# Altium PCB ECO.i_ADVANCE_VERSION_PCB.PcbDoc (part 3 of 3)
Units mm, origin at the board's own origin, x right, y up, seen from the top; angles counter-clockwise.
Board outline 291.08 x 101.6 mm, 4 copper layers (Top Layer, Layer 1, Layer 2, Bottom Layer), stack 1.161 mm thick; 272 components, 228 nets, 849 pads, 240 vias.
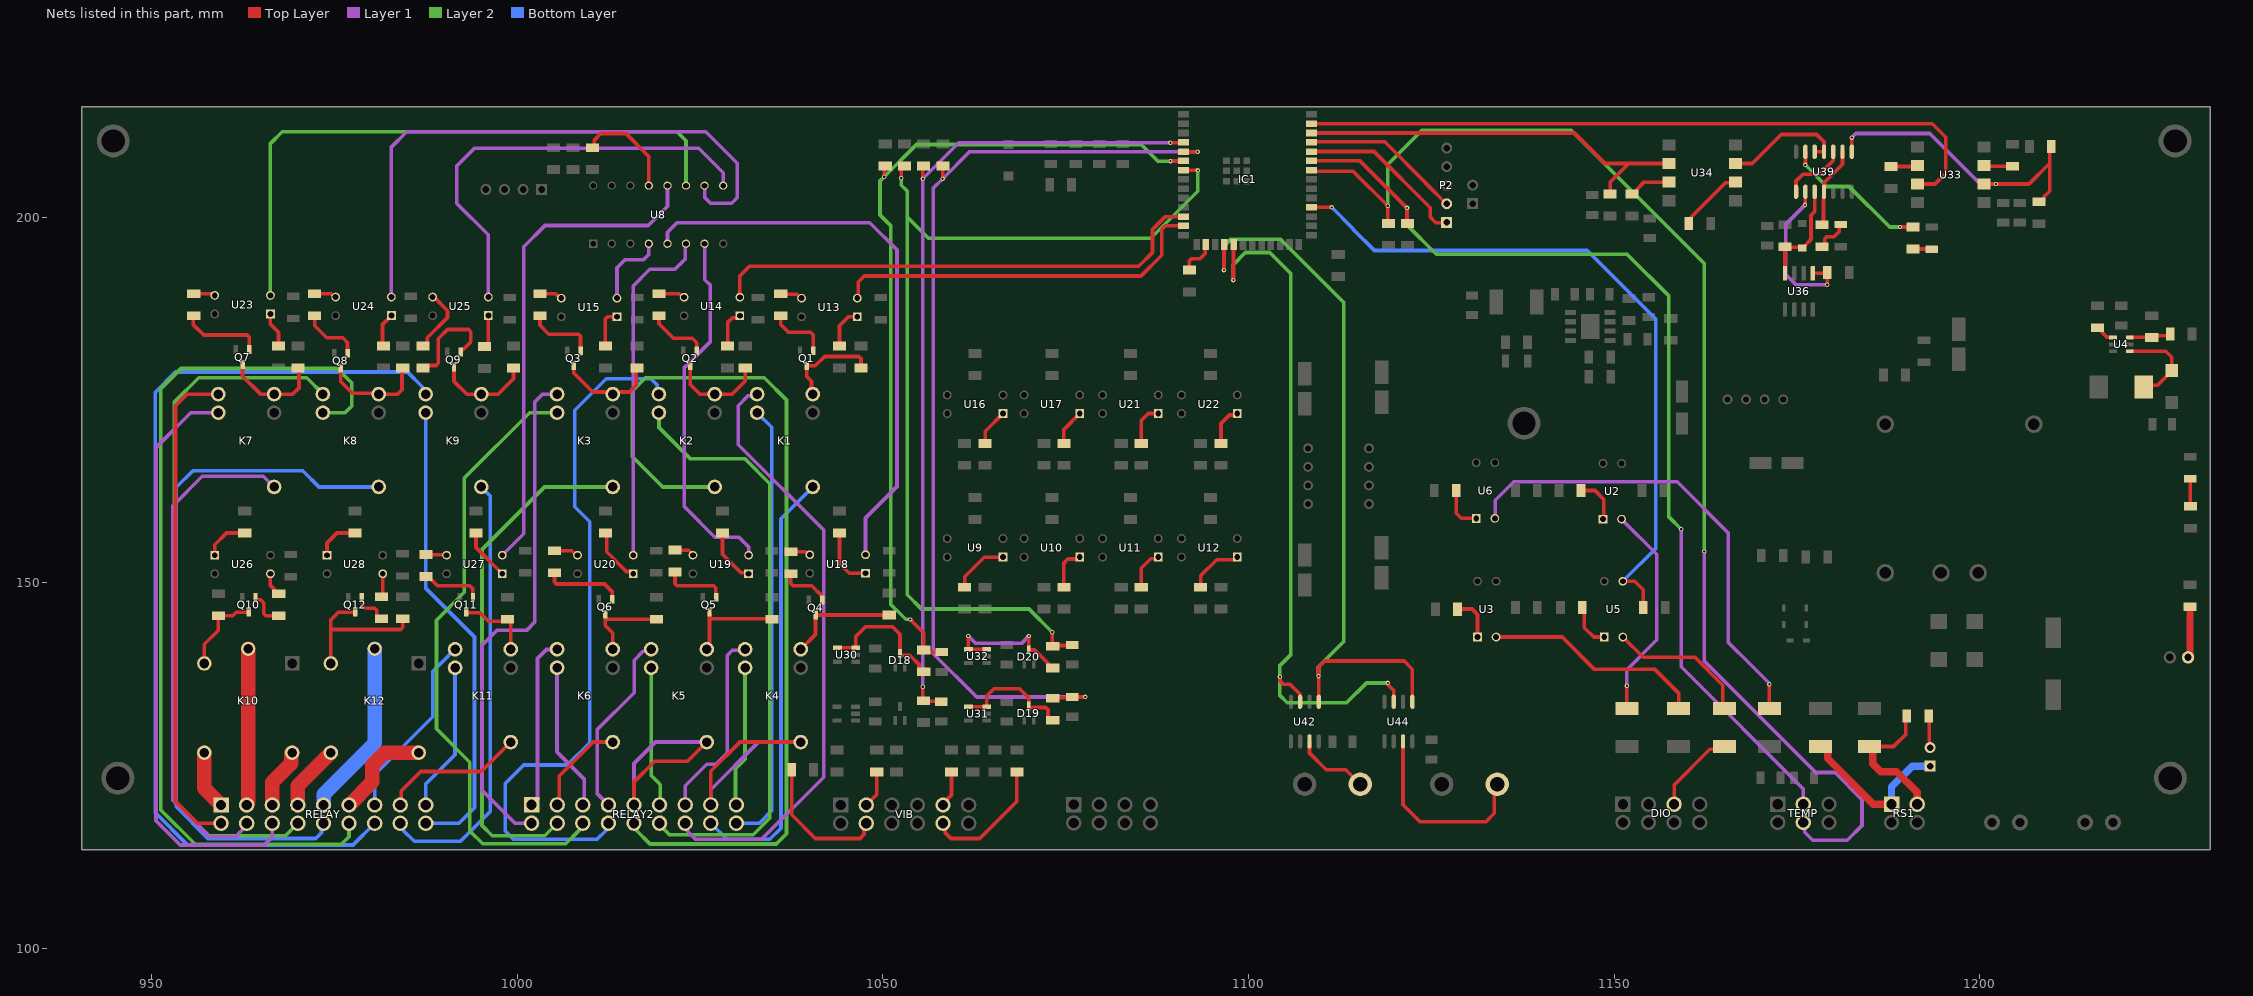
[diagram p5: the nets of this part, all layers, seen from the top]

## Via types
v1: diameter 0.6, hole 0.3, Top Layer to Bottom Layer, 154 vias
v2: diameter 1.27, hole 0.711, Top Layer to Bottom Layer, 80 vias
v3: diameter 2.4, hole 1.6, Top Layer to Bottom Layer, 4 vias
v4: diameter 1.5, hole 1, Top Layer to Bottom Layer, 2 vias

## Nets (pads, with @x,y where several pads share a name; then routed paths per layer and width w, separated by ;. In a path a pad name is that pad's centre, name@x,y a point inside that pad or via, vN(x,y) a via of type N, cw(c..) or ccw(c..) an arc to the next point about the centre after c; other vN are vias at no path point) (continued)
NetD18_3: D18.3 R84.1 U30.3 U30.4 | length 18.5
  Top Layer w0.5: U30.4@1043.774,141.128 U30.3@1046.285,141.128 1046.285,142.68 1047.623,144.018 1051.306,144.018 1052.347,142.977 D18.3@1052.347,140.354 1052.347,140.127 1053.673,140.127 1054.942,138.858 1054.942,138.195 1055.292,137.845 R84.1@1055.592,137.845
NetD19_3: D19.3 R90.1 U31.3 U31.4 | length 16.6
  Top Layer w0.5: U31.4@1061.691,133.081 U31.3@1064.201,133.081 1064.201,134.561 1065.149,135.509 1068.705,135.509 1069.961,134.253 1069.961,132.969 1072.274,132.969 1072.567,132.676 1072.567,131.58 1072.917,131.23 R90.1@1073.217,131.23
NetD20_3: D20.3 R91.1 U32.3 U32.4 | length 19.8
  Top Layer w0.5: v1(1061.673,142.738) 1061.673,140.975 1061.697,140.951 U32.4@1061.691,140.945 U32.3@1064.201,140.945 ; v1(1069.961,142.748) D20.3@1069.961,140.83 1070.741,140.83 1072.567,139.003 1072.567,138.703 1072.917,138.353 R91.1@1073.217,138.353
  Layer 1 w0.5: v1(1061.673,142.738) 1062.678,141.732 1068.945,141.732 v1(1069.961,142.748)
NetD21_2: D21.2 L2.1 U4.1 | length 12.7
  Top Layer w0.5: U4.1@1220.487,181.676 1225.416,181.676 1226.238,180.854 D21.2@1226.238,179.043 1226.238,178.993 1224.296,177.051 1222.656,177.051 L2.1@1222.416,176.811
NetD22_POS: D22.POS R107.2 | length 4.7
  Top Layer w0.5: R107.2@1178.427,195.985 1178.464,195.985 1178.814,196.335 1178.814,197.065 1179.107,197.358 1180.084,197.358 1180.78,198.054 1180.78,198.8 D22.POS@1180.996,199.016
NetD23_POS: D23.POS R111.1 | length 2.6
  Top Layer w0.5: R111.1@1190.869,195.66 1190.874,195.655 1193.433,195.655 D23.POS@1193.439,195.65
NetD24_1: D24.1 R113.1 U36.4 U39.10 | length 14.6
  Top Layer w0.5: U36.4@1173.353,192.335 R113.1@1173.353,195.985 1173.449,195.889 1175.628,195.889 D24.1@1175.725,195.793 1175.825,195.793 1176.05,196.018 1176.05,196.118 1176.909,196.977 1176.909,200.279 1177.41,200.78 U39.10@1177.41,203.497
NetD25_NEG: D25.NEG R115.2 | length 3.8
  Top Layer w0.5: D25.NEG@1228.757,164.228 1228.757,160.53 R115.2@1228.797,160.49
NetF1_2: F1.2 U2.2 | length 29.6
  Top Layer w0.5: v1(1151.735,135.94) 1151.735,132.86 F1.2@1151.737,132.858
  Layer 1 w0.5: U2.2@1151.011,158.722 1155.827,153.906 1155.827,142.24 1151.735,138.148 v1(1151.735,135.94)
NetF2_2: F2.2 U3.2 | length 30.2
  Top Layer w0.5: U3.2@1133.851,142.604 1142.89,142.604 1147.318,138.176 1155.573,138.176 1158.806,134.943 F2.2@1158.806,132.858
NetF3_2: F3.2 U5.2 | length 19.7
  Top Layer w0.5: U5.2@1151.184,142.604 1153.961,139.827 1161.034,139.827 1164.844,136.017 1164.844,133.125 F3.2@1165.112,132.858
NetF4_2: F4.2 U6.2 | length 64.5
  Top Layer w0.5: F4.2@1171.22,132.858 v1(1171.22,136.144)
  Layer 1 w0.5: U6.2@1133.678,158.828 1133.729,158.879 1133.729,161.29 1136.269,163.83 1158.621,163.83 1165.606,156.845 1165.606,141.859 1168.654,138.811 v1@1171.194,136.271
NetF5_2: F5.2 P5.1 RS1.1 | length 22.5
  Top Layer w1: F5.2@1178.237,127.628 1178.797,127.628 1179.187,127.238 1179.187,125.992 1185.432,119.747 RS1.1@1187.928,119.747
  Bottom Layer w1: RS1.1@1187.928,119.747 1187.928,122.144 1190.735,124.951 P5.1@1193.192,124.951
NetF6_2: F6.2 R112.1 RS1.3 | length 20.1
  Top Layer w0.5: F6.2@1184.89,127.628 1188.205,127.628 1189.863,129.286 1189.863,131.675 R112.1@1190.014,131.826
  Top Layer w1: F6.2@1184.962,127.628 1185.352,127.238 1185.352,125.288 1186.451,124.189 1188.61,124.189 1191.428,121.371 RS1.3@1191.428,119.747
NetIC1_16: IC1.16 R93.1 | length 5.1
  Top Layer w0.5: R93.1@1091.909,192.78 1091.909,194.017 1092.202,194.31 1093.343,194.31 1094.1,195.067 1094.1,196.242 IC1.16@1094.166,196.307
NetK1_3: K1.3 Q1.3 R35.1 | length 13.6
  Top Layer w0.5: K1.3@1040.411,175.824 1040.229,176.006 1040.229,177.574 1039.579,178.224 Q1.3@1039.579,179.688 1040.748,179.688 1042.035,180.975 1046.708,180.975 1047.001,180.682 R35.1@1047.001,179.392
NetK2_3: K2.3 Q2.3 R36.1 | length 13.1
  Top Layer w0.5: Q2.3@1023.644,179.688 1023.644,177.141 1024.961,175.824 K2.3@1026.998,175.824 1029.391,175.824 1031.175,177.608 R36.1@1031.175,179.392
NetK3_3: K3.3 Q3.3 R38.1 | length 13.6
  Top Layer w0.5: Q3.3@1007.745,179.713 1007.745,178.689 1010.323,176.111 1012.77,176.111 K3.3@1013.057,175.824 1013.344,176.111 1015.327,176.111 1016.254,177.038 1016.254,179.255 R38.1@1016.391,179.392
NetK4_3: K4.3 Q4.3 R50.1 | length 14.8
  Top Layer w0.5: K4.3@1038.771,140.941 1040.793,142.963 1040.793,145.602 1040.808,145.617 1050.051,145.617 R50.1@1050.056,145.622
NetK5_3: K5.3 Q5.3 R51.1 | length 13.3
  Top Layer w0.5: K5.3@1025.929,140.941 1026.216,141.228 1026.216,141.911 1026.289,141.984 1026.289,145.103 ; Q5.3@1026.289,145.995 1026.289,145.103 ; R51.1@1034.33,145.035 1034.262,145.103 1026.289,145.103
NetK6_3: K6.3 Q6.3 R53.1 | length 11.4
  Top Layer w0.5: K6.3@1013.057,140.941 1013.057,143.151 1012.056,144.152 1012.056,144.938 1012.16,145.041 R53.1@1019.029,145.041
NetK7_3: K7.3 Q7.3 R65.1 | length 13.4
  Top Layer w0.5: Q7.3@962.438,179.867 962.438,178.276 964.89,175.824 969.32,175.824 970.153,176.657 970.153,179.276 R65.1@970.037,179.392
NetK8_3: K8.3 Q8.3 R66.1 | length 14.3
  Top Layer w0.5: Q8.3@975.877,179.382 975.877,177.537 977.457,175.957 980.92,175.957 K8.3@981.053,175.824 983.671,175.824 984.25,176.403 R66.1@984.25,179.288 ; R66.1@984.057,179.392 R66.1@984.354,179.392
NetK9_3: K9.3 Q9.3 R69.1 | length 13.2
  Top Layer w0.5: Q9.3@991.351,179.529 991.351,177.557 993.084,175.824 997.387,175.824 999.488,177.925 R69.1@999.488,179.392
NetK10_A2: K10.A2 Q10.3 R75.1 | length 11.7
  Top Layer w0.5: K10.A2@957.212,138.991 957.212,141.618 959.104,143.51 959.104,145.457 R75.1@959.168,145.52 961.115,145.52 961.59,145.995 Q10.3@963.292,145.995
NetK11_3: K11.3 Q11.3 R77.1 | length 10.5
  Top Layer w0.5: Q11.3@993.034,145.923 994.918,145.923 996.061,144.78 998.41,144.78 R77.1@998.665,145.035 998.763,145.035 999.113,144.685 K11.3@999.113,140.941
NetK12_A2: K12.A2 Q12.3 R78.1 | length 20.8
  Top Layer w0.5: K12.A2@974.51,138.991 974.51,143.637 ; Q12.3@977.823,145.995 975.559,145.995 974.51,144.946 974.51,143.637 ; R78.1@984.347,145.114 984.347,143.93 984.054,143.637 974.51,143.637
NetP3_2: P3.2 R116.1 | length 6.9
  Top Layer w1: P3.2@1228.727,139.829 R116.1@1228.727,146.747
NetP5_2: P5.2 R112.2 | length 4.4
  Top Layer w0.5: R112.2@1193.014,131.826 1193.103,131.737 1193.103,127.58 P5.2@1193.192,127.491
NetQ1_1: Q1.1 R37.2 | length 8.4
  Top Layer w0.5: R37.2@1036.033,186.548 1036.033,185.326 1037.082,184.277 1040.13,184.277 1040.494,183.913 Q1.1@1040.494,181.738
NetQ2_1: Q2.1 R39.2 | length 8.4
  Top Layer w0.5: R39.2@1019.394,186.548 1019.394,185.455 1021.373,183.476 1023.913,183.476 1024.559,182.83 Q2.1@1024.559,181.738
NetQ3_1: Q3.1 R40.2 | length 9.9
  Top Layer w0.5: R40.2@1003.115,186.531 1003.115,185.224 1004.316,184.023 1008.367,184.023 1008.66,183.73 Q3.1@1008.66,181.302
NetQ4_1: Q4.1 R52.2 | length 6.9
  Top Layer w0.5: R52.2@1037.422,151.267 1037.422,149.899 1037.715,149.606 1040.257,149.606 1041.663,148.2 1041.663,147.717 Q4.1@1041.718,147.662
NetQ5_1: Q5.1 R54.2 | length 8.7
  Top Layer w0.5: R54.2@1021.566,151.487 1021.566,149.901 1021.858,149.608 1026.856,149.608 1027.149,149.315 1027.149,148.1 Q5.1@1027.204,148.045
NetQ6_1: Q6.1 R55.2 | length 10.7
  Top Layer w0.5: R55.2@1005.089,151.402 1005.089,150.153 1005.381,149.86 1011.936,149.86 1012.971,148.825 Q6.1@1012.971,147.773
NetQ7_1: Q7.1 R67.2 | length 11.3
  Top Layer w0.5: R67.2@955.757,186.548 955.675,186.466 955.675,185.346 957.125,183.896 963.061,183.896 963.353,183.603 Q7.1@963.353,181.917
NetQ8_1: Q8.1 R68.2 | length 8.2
  Top Layer w0.5: R68.2@972.297,186.548 972.297,185.181 973.963,183.515 976.122,183.515 976.792,182.845 Q8.1@976.792,181.432
NetQ9_1: Q9.1 R70.2 | length 13.7
  Top Layer w0.5: R70.2@987.697,179.392 988.044,179.739 988.91,179.739 989.203,180.032 989.203,183.388 990.473,184.658 993.355,184.658 993.648,184.365 993.648,182.961 992.606,181.919 992.321,181.919 992.266,181.864 Q9.1@992.266,181.579
NetQ10_1: Q10.1 R76.2 | length 5.3
  Top Layer w0.5: Q10.1@964.207,148.045 964.207,147.76 964.262,147.705 964.903,147.705 965.327,147.281 965.327,145.813 965.62,145.52 R76.2@967.388,145.52
NetQ11_1: Q11.1 R79.2 | length 8.5
  Top Layer w0.5: R79.2@987.528,150.877 987.828,150.877 989.099,149.606 993.521,149.606 993.894,149.233 993.894,147.856 Q11.1@993.949,147.801
NetQ12_1: Q12.1 R80.2 | length 5
  Top Layer w0.5: Q12.1@978.739,148.045 978.794,147.99 978.794,146.934 979.2,146.528 980.516,146.528 980.809,146.235 980.809,145.464 981.159,145.114 R80.2@981.459,145.114
NetR5_1: R5.1 U3.1 | length 6.1
  Top Layer w0.5: R5.1@1128.559,146.414 1128.576,146.431 1130.554,146.431 1131.311,145.674 U3.1@1131.311,142.604
NetR6_1: R6.1 U2.1 | length 6.4
  Top Layer w0.5: R6.1@1145.47,162.638 1147.367,162.638 1148.588,161.417 1148.588,158.838 U2.1@1148.471,158.722
NetR13_1: R13.1 U6.1 | length 6.2
  Top Layer w0.5: R13.1@1128.386,162.638 1128.386,159.521 1129.079,158.828 U6.1@1131.138,158.828
NetR14_1: R14.1 U5.1 | length 6.1
  Top Layer w0.5: R14.1@1145.642,146.643 1145.921,146.364 1145.921,143.891 1147.208,142.604 U5.1@1148.644,142.604
NetR17_2: R17.2 U8.13 | length 14.3
  Top Layer w0.5: R17.2@1010.301,209.52 1010.55,209.768 1010.55,210.577 1011.428,211.455 1014.858,211.455 1017.997,208.317 U8.13@1017.997,204.332
NetR24_1: R24.1 U9.1 | length 7.8
  Top Layer w0.5: R24.1@1061.175,149.423 1061.175,150.839 1063.865,153.529 U9.1@1066.421,153.529
NetR25_1: R25.1 U10.1 | length 5.8
  Top Layer w0.5: R25.1@1074.752,149.423 1074.752,152.732 1075.29,153.27 1076.668,153.27 U10.1@1076.927,153.529
NetR26_1: R26.1 U13.1 | length 5.7
  Top Layer w0.5: R26.1@1044.069,182.392 1044.069,185.168 1045.304,186.403 U13.1@1046.499,186.403
NetR29_1: R29.1 U14.1 | length 5.3
  Top Layer w0.5: R29.1@1028.762,182.392 1028.762,185.609 1029.432,186.279 1030.185,186.279 U14.1@1030.439,186.533
NetR32_1: R32.1 U15.1 | length 5.4
  Top Layer w0.5: R32.1@1012.056,182.392 1012.056,186.11 1012.349,186.403 U15.1@1013.638,186.403
NetR33_1: R33.1 U11.1 | length 5.5
  Top Layer w0.5: R33.1@1085.337,149.423 1085.337,152.014 1086.626,153.303 1087.436,153.303 U11.1@1087.662,153.529
NetR34_1: R34.1 U12.1 | length 7.6
  Top Layer w0.5: R34.1@1093.43,149.423 1093.47,149.464 1093.47,151.003 1095.646,153.179 1098.101,153.179 U12.1@1098.451,153.529
NetR37_1: R37.1 U13.3 | length 3.1
  Top Layer w0.5: R37.1@1036.033,189.548 1036.097,189.484 1038.236,189.484 1038.777,188.943 U13.3@1038.879,188.943
NetR39_1: R39.1 U14.3 | length 3.6
  Top Layer w0.5: R39.1@1019.394,189.548 1022.154,189.548 1022.63,189.073 U14.3@1022.819,189.073
NetR40_1: R40.1 U15.3 | length 3.1
  Top Layer w0.5: R40.1@1003.115,189.531 1005.241,189.531 1005.829,188.943 U15.3@1006.018,188.943
NetR45_1: R45.1 U16.1 | length 5.1
  Top Layer w0.5: R45.1@1063.984,169.081 1063.984,170.73 U16.1@1066.421,173.167
NetR46_1: R46.1 U17.1 | length 5
  Top Layer w0.5: R46.1@1074.752,169.081 1074.752,170.991 U17.1@1076.927,173.167
NetR47_1: R47.1 U18.1 | length 8.3
  Top Layer w0.5: R47.1@1044.069,156.831 1044.069,152.652 1045.403,151.318 U18.1@1047.625,151.318
NetR48_1: R48.1 U19.1 | length 7.6
  Top Layer w0.5: R48.1@1028.067,156.831 1028.067,153.922 1030.583,151.406 1031.491,151.406 U19.1@1031.64,151.257
NetR49_1: R49.1 U20.1 | length 7.5
  Top Layer w0.5: R49.1@1012.056,156.831 1012.246,156.641 1012.246,154.249 1014.922,151.573 1015.55,151.573 U20.1@1015.866,151.257
NetR52_1: R52.1 U18.3 | length 2.8
  Top Layer w0.5: R52.1@1037.422,154.267 1039.407,154.267 1039.816,153.858 U18.3@1040.005,153.858
NetR54_1: R54.1 U19.3 | length 2.9
  Top Layer w0.5: R54.1@1021.566,154.487 1023.438,154.487 1024.159,153.766 U19.3@1024.168,153.766
NetR55_1: R55.1 U20.3 | length 3.4
  Top Layer w0.5: R55.1@1005.089,154.402 1007.452,154.402 1008.057,153.797 U20.3@1008.246,153.797
NetR60_1: R60.1 U21.1 | length 5.8
  Top Layer w0.5: R60.1@1085.337,169.081 1085.337,172.207 1086.297,173.167 U21.1@1087.662,173.167
NetR61_1: R61.1 U22.1 | length 5.5
  Top Layer w0.5: R61.1@1096.226,169.081 1096.226,171.793 1097.395,172.962 1098.246,172.962 U22.1@1098.451,173.167
NetR62_1: R62.1 U23.1 | length 4.8
  Top Layer w0.5: U23.1@966.248,186.778 966.248,185.388 967.361,184.275 R62.1@967.361,182.392
NetR63_1: R63.1 U24.1 | length 4.7
  Top Layer w0.5: R63.1@981.709,182.392 981.583,182.518 981.583,185.346 U24.1@982.79,186.553
NetR64_1: R64.1 U25.1 | length 4.5
  Top Layer w0.5: R64.1@995.521,182.342 995.696,182.342 996.046,182.692 U25.1@996.046,186.553
NetR67_1: R67.1 U23.3 | length 3
  Top Layer w0.5: R67.1@955.757,189.548 958.209,189.548 958.439,189.318 U23.3@958.628,189.318
NetR68_1: R68.1 U24.3 | length 3.1
  Top Layer w0.5: R68.1@972.297,189.548 974.525,189.548 974.98,189.093 U24.3@975.17,189.093
NetR70_1: R70.1 U25.3 | length 8.8
  Top Layer w0.5: R70.1@987.697,182.392 987.697,183.533 990.473,186.309 990.473,187.235 988.615,189.093 U25.3@988.426,189.093
NetR72_1: R72.1 U26.1 | length 6.2
  Top Layer w0.5: U26.1@958.628,153.797 958.628,155.226 960.233,156.831 R72.1@962.742,156.831
NetR73_1: R73.1 U27.1 | length 7.1
  Top Layer w0.5: R73.1@994.363,156.831 994.363,154.852 U27.1@997.959,151.257
NetR74_1: R74.1 U28.1 | length 6.1
  Top Layer w0.5: U28.1@973.989,153.797 973.989,155.474 975.346,156.831 R74.1@977.823,156.831
NetR76_1: R76.1 U26.3 | length 3.4
  Top Layer w0.5: U26.3@966.248,151.257 966.248,149.66 966.738,149.17 966.738,148.87 967.088,148.52 R76.1@967.388,148.52
NetR79_1: R79.1 U27.3 | length 3.1
  Top Layer w0.5: R79.1@987.528,153.877 987.568,153.837 990.513,153.837 U27.3@990.553,153.797
NetR80_1: R80.1 U28.3 | length 3.2
  Top Layer w0.5: R80.1@981.459,148.114 981.609,148.264 U28.3@981.609,151.257
NetR98_1: R98.1 U4.4 | length 2.8
  Top Layer w0.5: R98.1@1216.069,184.904 1216.369,184.904 1216.719,184.554 1216.719,184.254 1217.381,183.592 1218.173,183.592 U4.4@1218.189,183.576
NetR99_1: R99.1 R100.2 U4.3 | length 5.8
  Top Layer w0.5: U4.3@1220.487,183.604 1223.411,183.604 R100.2@1223.497,183.518 ; R100.2@1223.497,183.549 1223.755,183.806 1225.815,183.806 R99.1@1226.027,184.019
NetR101_1: R101.1 U33.7 | length 4
  Top Layer w0.5: U33.7@1200.595,207.113 U33.7@1200.571,207.089 1200.683,206.977 R101.1@1204.472,206.977
NetR102_2: R102.2 U33.2 | length 3.7
  Top Layer w0.5: R102.2@1187.872,206.947 1191.339,206.947 U33.2@1191.481,207.089
NetR103_1: R103.1 U34.7 | length 5.9
  Top Layer w0.5: R103.1@1152.455,203.184 1152.755,203.184 1153.105,203.534 1153.105,203.834 1154.083,204.812 U34.7@1157.474,204.812
NetR105_2: R105.2 U34.2 | length 9.4
  Top Layer w0.5: R105.2@1160.066,198.882 1160.416,199.232 1160.416,199.915 1165.217,204.716 1166.468,204.716 U34.2@1166.564,204.812
NetR111_2: R111.2 U39.6 | length 20.1
  Top Layer w0.5: v1(1176.118,207.168) 1176.155,207.205 1176.155,208.95 U39.6@1176.14,208.965 ; v1(1189.081,198.667) 1189.085,198.664 1190.866,198.664 R111.2@1190.869,198.66
  Layer 2 w0.5: v1(1176.118,207.168) 1179.07,204.216 1182.116,204.216 1187.665,198.667 v1(1189.081,198.667)
NetU41_2: U41.2 U42.3 | length 10.3
  Top Layer w0.5: U42.3@1108.329,128.337 1108.329,126.746 1110.615,124.46 1113.296,124.46 U41.2@1115.28,122.476
NetU43_2: U43.2 U44.3 | length 26.7
  Top Layer w0.5: U44.3@1121.125,128.337 1121.125,119.665 1123.442,117.348 1132.459,117.348 1133.602,118.491 1133.602,122.059 U43.2@1134.019,122.477
R1_C: K1.1 RELAY2.16 | length 59.6
  Bottom Layer w0.5: RELAY2.16@1026.463,117.154 1028.682,114.935 1034.542,114.935 1036.066,116.459 1036.066,158.779 K1.1@1040.411,163.124
R1_NC: K1.5 RELAY2.18 | length 60.8
  Bottom Layer w0.5: RELAY2.18@1029.963,117.154 1033.078,117.154 1034.796,118.872 1034.796,171.279 K1.5@1032.791,173.284
R1_NO: K1.4 RELAY2.14 | length 82.7
  Layer 1 w0.5: RELAY2.14@1022.963,117.154 1023.27,116.848 1023.27,116.047 1024.382,114.935 1033.399,114.935 1041.908,123.444 1041.908,157.226 1030.224,168.91 1030.224,174.244 1031.56,175.58 1032.547,175.58 K1.4@1032.791,175.824
R2_C: K2.1 RELAY2.10 | length 127.4
  Layer 2 w0.5: RELAY2.10@1015.963,117.154 1016.27,116.848 1016.27,116.189 1018.165,114.294 1035.425,114.294 1036.828,115.697 1036.828,175.006 1033.78,178.054 1017.524,178.054 1015.746,176.276 1015.746,167.259 1019.881,163.124 K2.1@1026.998,163.124
R2_NC: K2.5 RELAY2.12 | length 82.9
  Layer 2 w0.5: K2.5@1019.378,173.284 1019.378,171.247 1023.62,167.005 1031.113,167.005 1034.542,163.576 1034.542,117.856 1032.256,115.57 1020.826,115.57 1019.463,116.933 RELAY2.12@1019.463,117.154
R2_NO: K2.4 RELAY2.8 | length 97.3
  Bottom Layer w0.5: RELAY2.8@1012.463,117.154 1012.157,116.848 1012.157,116.172 1010.92,114.935 999.49,114.935 998.355,116.07 998.355,122.563 1000.887,125.095 1006.856,125.095 1009.904,128.143 1009.904,158.369 1007.872,160.401 1007.872,173.609 1012.182,177.919 1018.294,177.919 1019.146,177.067 1019.146,176.056 K2.4@1019.378,175.824
R3_C: K3.1 RELAY2.4 | length 70.7
  Layer 2 w0.5: RELAY2.4@1005.463,117.154 1003.752,115.443 996.569,115.443 995.172,116.84 995.172,154.559 1003.737,163.124 K3.1@1013.057,163.124
R3_NC: K3.5 RELAY2.6 | length 85.7
  Layer 2 w0.5: K3.5@1005.437,173.284 1001.705,173.284 992.759,164.338 992.759,148.717 988.949,144.907 988.949,130.048 993.521,125.476 993.521,116.078 995.269,114.33 1006.632,114.33 1008.437,116.135 1008.437,116.194 1008.963,116.721 RELAY2.6@1008.963,117.154
R3_NO: K3.4 RELAY2.2 | length 70.6
  Layer 1 w0.5: RELAY2.2@1001.963,117.154 999.684,117.154 995.172,121.666 995.172,141.478 997.204,143.51 1001.268,143.51 1002.411,144.653 1002.411,174.752 1003.483,175.824 K3.4@1005.437,175.824
R4_C: K4.1 RELAY2.15 | length 35.6
  Top Layer w0.5: RELAY2.15@1026.463,119.654 1026.463,124.255 1030.449,128.241 K4.1@1038.771,128.241
  Layer 1 w0.5: RELAY2.15@1026.463,119.654 1026.463,121.715 1032.989,128.241 K4.1@1038.771,128.241
R4_NC: K4.5 RELAY2.17 | length 19.7
  Layer 1 w0.5: RELAY2.17@1029.963,119.654 RELAY2.17@1030.224,119.915
  Layer 2 w0.5: RELAY2.17@1029.963,119.654 1029.843,119.774 1029.843,124.587 1031.151,125.895 K4.5@1031.151,138.401
R4_NO: K4.4 RELAY2.13 | length 26.4
  Layer 1 w0.5: RELAY2.13@1022.963,119.654 1022.963,122.279 1025.906,125.222 1027.176,125.222 1028.7,126.746 1028.7,140.081 1029.401,140.782 1030.993,140.782 K4.4@1031.151,140.941
R5_C: K5.1 RELAY2.9 | length 32.2
  Top Layer w0.5: RELAY2.9@1015.963,119.654 1015.963,122.772 1018.794,125.603 1023.291,125.603 K5.1@1025.929,128.241
  Layer 1 w0.5: RELAY2.9@1015.963,119.654 1015.963,125.312 1018.892,128.241 K5.1@1025.929,128.241
R5_NC: K5.5 RELAY2.11 | length 19.3
  Layer 2 w0.5: K5.5@1018.309,138.401 1018.309,123.675 1019.556,122.428 1019.556,119.747 RELAY2.11@1019.463,119.654
R5_NO: K5.4 RELAY2.7 | length 25.5
  Layer 1 w0.5: RELAY2.7@1012.463,119.654 1010.92,121.197 1010.92,129.921 1016,135.001 1016,139.446 1017.208,140.654 1018.022,140.654 K5.4@1018.309,140.941
R6_C: K6.1 RELAY2.3 | length 13.3
  Top Layer w0.5: RELAY2.3@1005.463,119.654 1005.74,119.931 1005.74,123.598 1010.383,128.241 K6.1@1013.057,128.241
R6_NC: K6.5 RELAY2.5 | length 20.4
  Layer 1 w0.5: K6.5@1005.437,138.401 1005.437,126.895 1009.142,123.19 1009.142,119.833 RELAY2.5@1008.963,119.654
R6_NO: K6.4 RELAY2.1 | length 23.5
  Layer 1 w0.5: RELAY2.1@1001.963,119.654 1002.763,120.454 1002.763,139.671 1003.998,140.906 1005.402,140.906 K6.4@1005.437,140.941
R7_C: K9.1 RELAY.16 | length 60.2
  Bottom Layer w0.5: RELAY.16@984.001,117.134 984.001,116.701 984.497,116.205 984.497,116.085 985.901,114.681 992.251,114.681 996.315,118.745 996.315,161.899 K9.1@995.09,163.124
R7_NC: K9.5 RELAY.18 | length 64.3
  Bottom Layer w0.5: K9.5@987.47,173.284 987.47,149.307 994.156,142.621 994.156,119.253 992.037,117.134 RELAY.18@987.501,117.134
R7_NO: K9.4 RELAY.14 | length 130.2
  Bottom Layer w0.5: RELAY.14@980.501,117.134 977.54,114.173 954.913,114.173 950.488,118.598 950.488,176.042 953.283,178.837 984.991,178.837 987,176.828 987,176.7 987.47,176.23 K9.4@987.47,175.824
R8_C: K8.1 RELAY.10 | length 96.6
  Bottom Layer w0.5: RELAY.10@973.501,117.134 973.233,116.866 973.233,115.856 972.439,115.062 957.707,115.062 953.389,119.38 953.389,163.068 955.675,165.354 970.661,165.354 972.891,163.124 K8.1@981.053,163.124
R8_NC: K8.5 RELAY.12 | length 123.1
  Layer 2 w0.5: K8.5@973.433,173.284 976.432,173.284 977.392,174.244 977.392,177.292 975.36,179.324 954.024,179.324 951.23,176.53 951.23,119.003 955.98,114.253 975.948,114.253 977.001,115.306 RELAY.12@977.001,117.134
R8_NO: K8.4 RELAY.8 | length 96.7
  Layer 2 w0.5: RELAY.8@970.001,117.134 968.31,115.443 957.834,115.443 953.135,120.142 953.135,174.752 956.437,178.054 971.203,178.054 K8.4@973.433,175.824
R9_C: K7.1 RELAY.4 | length 69.5
  Layer 1 w0.5: RELAY.4@963.001,117.134 963.001,116.819 961.468,115.285 957.907,115.285 952.881,120.311 952.881,160.528 956.945,164.592 965.279,164.592 K7.1@966.747,163.124
R9_NC: K7.5 RELAY.6 | length 81.2
  Layer 1 w0.5: K7.5@959.127,173.284 955.35,173.284 950.595,168.529 950.595,117.475 953.909,114.161 965.442,114.161 966.501,115.22 RELAY.6@966.501,117.134
R9_NO: K7.4 RELAY.2 | length 68.1
  Top Layer w0.5: K7.4@959.127,175.824 954.842,175.824 953.262,174.244 953.262,120.142 956.27,117.134 RELAY.2@959.501,117.134
R10_C: K11.1 RELAY.15 | length 19.7
  Top Layer w0.5: RELAY.15@984.001,119.634 984.123,119.756 984.123,121.539 986.79,124.206 995.078,124.206 K11.1@999.113,128.241
R10_NC: K11.5 RELAY.17 | length 20.4
  Bottom Layer w0.5: RELAY.17@987.501,119.634 987.501,122.504 991.493,126.496 K11.5@991.493,138.401
R10_NO: K11.4 RELAY.13 | length 25.9
  Bottom Layer w0.5: RELAY.13@980.501,119.634 980.501,123.773 988.441,131.712 988.441,137.889 K11.4@991.493,140.941
R11_C: K12.COM RELAY.9 | length 24.3
  Bottom Layer w2: RELAY.9@973.501,119.634 973.52,119.653 973.52,121.092 980.51,128.082 K12.COM@980.51,140.991
R11_NC: K12.NC RELAY.11 | length 13.8
  Top Layer w2: RELAY.11@977.001,119.634 980.186,122.819 980.186,125.095 981.882,126.791 K12.NC@986.51,126.791
R11_NO: K12.NO RELAY.7 | length 9
  Top Layer w2: RELAY.7@970.001,119.634 970.001,122.282 K12.NO@974.51,126.791
R12_C: K10.COM RELAY.3 | length 21.4
  Top Layer w2: RELAY.3@963.001,119.634 963.001,119.796 963.212,120.007 K10.COM@963.212,140.991
R12_NC: K10.NC RELAY.5 | length 8.3
  Top Layer w2: RELAY.5@966.501,119.634 966.501,122.713 969.12,125.332 969.12,126.699 K10.NC@969.212,126.791
R12_NO: K10.NO RELAY.1 | length 8.1
  Top Layer w2: K10.NO@957.212,126.791 957.212,121.924 RELAY.1@959.501,119.634
R_1: IC1.13 U13.2 | length 52
  Top Layer w0.5: U13.2@1046.499,188.943 1046.607,189.051 1046.607,191.135 1047.441,191.969 1048.131,191.969 1085.287,191.969 1088.136,194.818 1088.136,198.319 1088.644,198.827 IC1.13@1091.131,198.827
R_2: IC1.12 U14.2 | length 68.8
  Top Layer w0.5: U14.2@1030.439,189.073 1030.439,191.985 1031.758,193.304 1084.971,193.304 1086.866,195.199 1086.866,198.319 1088.644,200.097 IC1.12@1091.131,200.097
R_3: U8.4 U15.2 | length 10.7
  Layer 1 w0.5: U15.2@1013.638,188.943 1013.638,193.091 1014.73,194.183 1017.27,194.183 1017.997,194.91 U8.4@1017.997,196.392
R_4: U8.5 U18.2 | length 78.5
  Layer 1 w0.5: U8.5@1020.537,196.392 1020.537,197.958 1021.842,199.263 1048.215,199.263 1051.925,195.553 1051.925,163.179 1047.625,158.879 U18.2@1047.625,153.858
R_5: U8.7 U19.2 | length 50
  Layer 1 w0.5: U8.7@1025.617,196.392 1025.652,196.357 1025.652,191.451 1026.414,190.689 1026.414,183.007 1022.858,179.451 1022.858,160.401 1027.021,156.238 1030.323,156.238 1031.64,154.921 U19.2@1031.64,153.797
R_6: U8.6 U20.2 | length 47.6
  Layer 1 w0.5: U20.2@1015.866,153.797 1015.866,190.62 1018.127,192.881 1021.556,192.881 1022.956,194.281 1022.956,196.271 U8.6@1023.077,196.392
R_7: U8.9 U25.2 | length 60.2
  Layer 1 w0.5: U25.2@996.046,189.093 996.046,197.597 991.743,201.9 991.743,207.01 994.156,209.423 1024.81,209.423 1028.157,206.076 U8.9@1028.157,204.332
R_8: U8.10 U24.2 | length 81.9
  Layer 1 w0.5: U24.2@982.79,189.093 982.79,209.614 984.885,211.709 1025.779,211.709 1030.097,207.391 1030.097,202.692 1029.335,201.93 1026.414,201.93 1025.617,202.727 U8.10@1025.617,204.332
R_9: U8.11 U23.2 | length 84.9
  Layer 2 w0.5: U23.2@966.248,189.318 966.248,210.09 967.867,211.709 1021.842,211.709 1023.077,210.474 U8.11@1023.077,204.332
R_10: U8.12 U27.2 | length 68.1
  Layer 1 w0.5: U27.2@997.959,153.797 1000.887,156.725 1000.887,195.961 1003.808,198.882 1017.905,198.882 1020.537,201.514 U8.12@1020.537,204.332
RX0: IC1.36 P2.1 | length 23.3
  Top Layer w0.5: IC1.36@1108.631,208.987 1117.147,208.987 1124.839,201.295 1124.839,200.025 1125.611,199.253 P2.1@1127.111,199.253
RXD: R108.2 U36.1 U39.9 | length 22.4
  Top Layer w0.5: v1(1176.092,201.691) 1176.092,201.718 1176.141,201.767 1176.141,203.496 U39.9@1176.14,203.497 ; U36.1@1177.163,192.335 1179.029,192.335 R108.2@1179.136,192.442 1179.137,192.441 1179.137,190.776 v1(1179.139,190.775)
  Layer 1 w0.5: v1(1176.092,201.691) 1173.48,199.078 1173.48,192.151 1174.856,190.775 v1(1179.139,190.775)
RXD_1: IC1.38 R106.1 U34.6 | length 55.8
  Top Layer w0.5: IC1.38@1108.631,211.527 1144.579,211.527 1148.754,207.352 1151.978,207.352 ; R106.1@1149.447,203.184 1149.447,204.821 1151.978,207.352 ; U34.6@1157.474,207.352 1151.978,207.352
RXD_CD: U39.3 U39.8 | length 8.9
  Top Layer w0.5: U39.8@1174.87,203.497 1174.87,204.971 1175.766,205.867 1178.052,205.867 1179.95,207.765 U39.3@1179.95,208.965
SCK: IC1.18 U42.5 U44.5 | length 102.6
  Top Layer w0.5: v1(1096.634,192.774) 1096.634,196.236 IC1.18@1096.706,196.307 ; U42.5@1109.599,133.747 1109.599,137.186 1109.565,137.22 1109.565,138.523 1110.361,139.319 1121.283,139.319 1122.395,138.207 U44.5@1122.395,133.747
  Layer 2 w0.5: v1(1096.634,192.774) 1096.634,196.077 1097.534,196.977 1104.392,196.977 1113.028,188.341 1113.028,141.986 1109.565,138.523 v1(1109.565,137.247)
SENSOR1: R81.2 VIB.3 | length 5.1
  Top Layer w0.5: VIB.3@1047.725,119.634 1049.15,121.059 R81.2@1049.15,124.163
SENSOR2: R87.1 VIB.9 | length 5
  Top Layer w0.5: VIB.9@1058.225,119.634 1058.225,119.851 1059.39,121.015 R87.1@1059.39,124.163
SENSOR3: R82.1 VIB.4 | length 19.3
  Top Layer w0.5: R82.1@1037.523,124.463 1037.523,118.304 1040.765,115.062 1046.861,115.062 1047.419,115.62 1047.419,116.828 VIB.4@1047.725,117.134
SENSOR4: R89.1 VIB.10 | length 17.7
  Top Layer w0.5: VIB.10@1058.225,117.134 1058.503,116.856 1058.503,115.866 1059.307,115.062 1063.244,115.062 1068.322,120.14 R89.1@1068.322,124.163
SENSOR_1: C17.1 IC1.4 R83.2 R94.2 | length 113.1
  Top Layer w0.5: R94.2@1055.302,206.629 1055.466,206.465 R94.2@1055.463,206.462 ; v1(1055.45,135.8) 1055.45,133.985 1055.606,133.83 1057.91,133.83 C17.1@1057.985,133.755 ; v1(1055.463,205.27) R94.2@1055.463,206.462 ; v1(1089.306,210.196) 1089.325,210.215 1091.089,210.215 IC1.4@1091.131,210.257
  Layer 1 w0.5: v1(1055.45,135.8) 1055.457,135.806 1055.457,205.263 1060.39,210.196 v1(1089.306,210.196)
SENSOR_2: C22.1 IC1.5 R90.2 R95.2 | length 132.9
  Top Layer w0.5: v1@1058.165,205.27 v1(1058.167,205.272) 1058.17,205.275 R95.2@1058.17,206.629 ; R90.2@1073.217,134.23 1073.304,134.318 1075.776,134.318 1075.868,134.409 1077.678,134.409 v1(1077.682,134.413) ; IC1.5@1091.131,208.987 1091.153,209.01 1091.212,208.951 v1(1093.028,208.951)
  Layer 1 w0.5: v1(1077.682,134.413) 1062.816,134.413 1056.894,140.335 1056.894,203.999 v1(1058.167,205.272) 1061.846,208.951 v1(1093.028,208.951)
SENSOR_3: C16.1 IC1.6 R84.2 R96.2 | length 115.5
  Top Layer w0.5: v1@1050.177,205.539 v1(1050.18,205.542) 1050.182,205.544 R96.2@1050.182,206.898 ; v1(1053.748,145.003) 1053.753,145.003 1055.592,143.164 R84.2@1055.592,140.845 1055.893,140.544 C16.1@1058.051,140.544 ; v1(1089.324,207.677) 1089.343,207.697 1091.11,207.697 IC1.6@1091.131,207.717
  Layer 2 w0.5: v1(1053.748,145.003) 1053.729,145.022 1053.133,145.022 1051.052,147.104 1051.052,198.882 1049.609,200.325 1049.609,204.971 v1(1050.18,205.542) 1054.6,209.962 1085.311,209.962 1087.611,207.662 1089.308,207.662 v1(1089.324,207.677)
SENSOR_4: C21.1 IC1.7 R91.2 R97.2 | length 133.6
  Top Layer w0.5: v1@1052.517,205.337 v1(1052.52,205.34) 1052.522,205.342 R97.2@1052.522,206.697 ; v1(1073.15,143.256) 1073.15,141.42 R91.2@1073.217,141.353 1073.304,141.441 1075.776,141.441 C21.1@1075.864,141.528 ; IC1.7@1091.131,206.447 1091.158,206.42 1093.035,206.42 v1@1093.062,206.392
  Layer 2 w0.5: v1(1052.52,205.34) 1052.52,204.399 1053.338,203.581 1053.338,200.025 ; v1(1073.15,143.256) 1069.975,146.431 1055.288,146.431 1053.338,148.381 1053.338,200.025 ; v1@1093.062,206.392 1093.062,203.554 1086.631,197.123 1056.24,197.123 1053.338,200.025
  other v1: 1093.068,206.416
SMOKE_SENSOR_NO: DIO.5 F3.1 | length 11.7
  Top Layer w0.5: DIO.5@1158.193,119.747 1158.193,122.381 1163.08,127.268 1164.751,127.268 F3.1@1165.112,127.628
SMOKE_SENSOR_SIG: IC1.30 R15.2 U5.3 | length 96.8
  Top Layer w0.5: IC1.30@1108.631,201.367 1108.634,201.363 1111.385,201.363 v1(1111.388,201.359) ; U5.3@1151.184,150.224 1152.796,150.224 1153.966,149.054 R15.2@1153.966,146.643
  Bottom Layer w0.5: v1(1111.388,201.359) 1114.298,198.45 1114.298,198.374 1117.219,195.453 1146.302,195.453 1155.7,186.055 1155.7,154.74 U5.3@1151.184,150.224
SO: IC1.19 U42.7 U44.7 | length 99.4
  Top Layer w0.5: v1(1097.926,191.416) 1097.946,191.436 1097.946,196.277 IC1.19@1097.976,196.307 ; v1(1104.289,137.184) 1104.289,136.628 1104.773,136.144 1105.678,136.144 1107.046,134.776 1107.046,133.76 U42.7@1107.059,133.747 ; v1(1119.055,136.326) 1119.055,136.086 1119.855,135.286 U44.7@1119.855,133.747
  Layer 2 w0.5: v1(1097.926,191.416) 1097.926,193.559 1099.549,195.182 1102.885,195.182 1105.789,192.278 1105.789,140.208 1104.289,138.708 v1(1104.289,137.184) 1104.289,134.596 1105.281,133.604 1113.409,133.604 1116.131,136.326 v1(1119.055,136.326)
Temp_1: IC1.34 R3.1 TEMP.4 | length 171.4
  Top Layer w0.5: IC1.34@1108.631,206.447 1108.8,206.277 1114.326,206.277 v1(1119.034,201.569) 1119.034,199.259 R3.1@1119.131,199.162
  Layer 1 w0.5: v1(1162.304,154.305) 1162.304,139.319 1177.544,124.079 1180.211,124.079 1183.894,120.396 1183.894,116.84 1181.862,114.808 1177.163,114.808 1176.068,115.903 1176.068,117.046 TEMP.4@1175.866,117.248
  Layer 2 w0.5: v1@1119.034,201.361 1119.034,207.206 1123.713,211.885 1144.094,211.885 1162.304,193.675 v1(1162.304,154.305)
Temp_2: IC1.35 R4.1 TEMP.3 | length 137.1
  Top Layer w0.5: IC1.35@1108.631,207.717 1108.639,207.709 1115.25,207.709 v1(1121.677,201.282) 1121.677,199.314 1121.753,199.238 1121.791,199.2 R4.1@1121.753,199.162
  Layer 1 w0.5: v1(1159.158,157.343) 1159.158,138.528 1175.866,121.82 TEMP.3@1175.866,119.747
  Layer 2 w0.5: v1@1121.677,201.214 1121.677,198.938 1125.67,194.945 1151.763,194.945 1157.478,189.23 1157.478,159.023 v1(1159.158,157.343)
TX0: IC1.37 P2.2 | length 22
  Top Layer w0.5: IC1.37@1108.631,210.257 1108.686,210.312 1118.616,210.312 1124.204,204.724 1124.204,204.7 P2.2@1127.111,201.793
TXD: R104.1 R109.2 U33.6 U39.1 | length 43.3
  Top Layer w0.5: v1(1182.476,210.895) 1182.483,210.888 1182.483,208.972 U39.1@1182.49,208.965 ; U33.6@1200.571,204.549 1206.706,204.549 1209.548,207.391 ; R109.2@1208.099,202.113 1208.399,202.113 1208.749,202.463 1208.749,202.763 1209.548,203.562 1209.548,207.391 ; R104.1@1209.776,209.677 1209.548,209.449 1209.548,207.391
  Layer 1 w0.5: v1(1182.476,210.895) 1183.035,211.455 1193.165,211.455 1200.068,204.552 v1(1202.165,204.552)
TXD_1: IC1.39 U33.3 | length 96.9
  Top Layer w0.5: IC1.39@1108.631,212.797 1193.474,212.797 1195.324,210.947 1195.324,205.994 1193.879,204.549 U33.3@1191.481,204.549
TXD_CD: R107.1 U39.2 U39.11 | length 11.1
  Top Layer w0.5: R107.1@1178.427,198.985 1178.627,199.185 1178.627,202.733 1178.68,202.785 1178.68,204.717 1181.22,207.257 U39.2@1181.22,208.965
~RXD_CD: U34.3 U39.4 U39.5 | length 16.8
  Top Layer w0.5: U34.3@1166.564,207.352 1168.869,207.352 1172.845,211.328 1177.671,211.328 1178.68,210.319 U39.4@1178.68,208.965 U39.5@1177.41,208.965
pads on no net: IC1.15 IC1.26 PS1.6 U4.6 U33.1 U33.4 U34.1 U34.4 U42.8 U44.8

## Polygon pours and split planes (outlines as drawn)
GND on Top Layer "GND_L01_P001" (solid, remove dead copper, pour order 1): 940.435,215.138 1231.519,215.138 1231.519,113.538 940.435,113.538
GND on Layer 1 "GND_L02_P002" (solid, remove dead copper, pour order 2): 940.435,215.138 1231.519,215.138 1231.519,113.538 940.435,113.538
GND on Layer 2 "GND_L03_P003" (solid, remove dead copper, pour order 3): 940.435,215.138 1231.519,215.138 1231.519,113.538 940.435,113.538
GND on Bottom Layer "GND_L04_P004" (solid, remove dead copper, pour order 4): 940.435,215.138 1231.519,215.138 1231.519,113.538 940.435,113.538

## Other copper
Top Layer:
  rectangle net +3.3V: 1120.14,188.849 1126.617,191.897
  rectangle net +5V: 1043.051,129.159 1045.083,131.479
  rectangle net +3.3V: 1122.045,127.381 1125.982,129.286
  rectangle net +3.3V: 1109.319,127.381 1112.012,129.348
  rectangle net +48V: 1203.325,159.766 1208.913,164.846
  rectangle net +5V: 1209.421,178.689 1216.406,182.753
  rectangle net +5V: 1208.52,182.377 1218.716,182.878
  rectangle net +5V: 1206.5,186.944 1220.47,189.738
  rectangle net +5V: 1200.785,170.434 1217.549,179.07
  rectangle net GND: 1183.894,159.258 1199.642,174.879
  rectangle net GND: 1194.308,165.617 1199.642,182.245
  rectangle net +5V: 1200.785,170.434 1209.802,187.327
  rectangle net +5V: 1184.275,182.626 1202.817,187.325
  rectangle net GND: 1172.337,165.608 1188.339,179.451
  rectangle net GND: 1153.85,185.252 1160.478,186.938
  rectangle net GND: 993.775,196.215 996.569,205.613
  rectangle net GND: 993.775,195.707 1016.127,197.358
  rectangle net GND: 1048.738,209.55 1066.927,210.82
  rectangle net GND: 1057.275,209.042 1066.038,210.185
  rectangle net GND: 1065.53,209.042 1083.811,210.82
  rectangle net GND: 1106.65,145.542 1112.012,151.638
  rectangle net GND: 1212.469,113.665 1215.644,121.793
  rectangle net GND: 1096.264,204.47 1100.328,208.28
  rectangle net GND: 1081.786,209.296 1083.818,214.502
  rectangle net GND: 1082.421,213.614 1091.819,214.503
  rectangle net GND: 1107.948,213.614 1115.695,214.503
  rectangle net GND: 1125.601,205.994 1128.649,210.82
  rectangle net +5V: 1140.587,185.293 1144.78,186.085
  rectangle net +5V: 1132.713,200.406 1143.127,204.47
  rectangle net +5V: 1113.409,177.546 1119.378,185.039
  rectangle net +5V: 1059.815,138.43 1062.355,139.7
  rectangle net +5V: 1059.307,131.318 1060.727,139.7
  rectangle net +5V: 1059.307,128.905 1060.577,131.064
  rectangle net +5V: 1059.307,129.667 1062.355,131.699
  rectangle net +5V: 1042.797,137.795 1044.448,139.7
  rectangle net +5V: 1038.098,137.795 1044.448,139.319
  rectangle net +5V: 980.694,152.953 985.52,154.813
  rectangle net +5V: 1026.922,165.608 1040.257,168.148
  rectangle net +5V: 1039.114,165.608 1041.4,174.371
  rectangle net +5V: 1013.46,165.608 1026.795,168.148
  rectangle net +5V: 1025.652,165.608 1027.938,174.371
  rectangle net +5V: 995.934,165.608 1000.633,168.148
  rectangle net +5V: 999.617,165.608 1012.952,168.148
  rectangle net +5V: 1011.809,165.608 1014.095,174.371
  rectangle net +5V: 981.71,165.608 995.045,168.148
  rectangle net +5V: 993.902,165.608 996.188,174.371
  rectangle net +5V: 965.581,165.608 967.867,174.371
  rectangle net +5V: 979.932,165.608 982.218,174.371
  rectangle net +5V: 967.486,165.608 981.075,168.148
  rectangle net +5V: 965.454,153.08 970.28,154.94
  rectangle net +5V: 1037.59,130.81 1039.876,139.573
  rectangle net +5V: 1025.398,130.81 1038.733,133.35
  rectangle net +5V: 1024.763,130.81 1027.049,139.573
  rectangle net +5V: 1012.571,130.81 1025.906,133.35
  rectangle net +5V: 999.744,130.81 1013.079,133.35
  rectangle net +5V: 1011.936,130.81 1014.222,139.573
  rectangle net +5V: 997.393,130.801 1000.441,139.505
  rectangle net +5V: 987.079,130.81 999.425,133.663
  rectangle net +5V: 966.597,133.223 971.169,142.494
  rectangle net +5V: 983.996,132.461 988.06,142.367
  rectangle net +5V: 966.611,130.81 988.103,136.525
  rectangle net +5V: 1191.387,182.626 1193.292,184.404
  rectangle net +3.3V: 1146.233,199.318 1153.343,200.774
  rectangle net +3.3V: 1002.411,202.565 1011.174,205.052
  rectangle net +3.3V: 1117.092,188.214 1135.761,197.036
  rectangle net +3.3V: 1132.84,186.563 1136.65,190.119
  rectangle net +3.3V: 1043.178,159.385 1045.222,180.058
  rectangle net +3.3V: 961.39,159.229 1045.246,161.036
  rectangle net +3.3V: 1084.453,206.883 1085.596,213.233
  rectangle net +3.3V: 1084.58,212.344 1091.819,213.233
  rectangle net +3.3V: 1081.913,206.629 1085.594,207.899
  rectangle net +3.3V: 1075.182,203.581 1080.135,205.486
  rectangle net +3.3V: 1078.611,203.581 1083.691,207.899
  region net +3.3V: 1011.174,207.155 1002.411,207.155 1002.411,203.835 1011.174,203.835
  rectangle net +3.3V: 1132.84,186.563 1136.646,197.05
  rectangle net +48V: 1214.247,146.812 1218.819,150.495
  region net NetD3_2: 1200.531,126.111 1200.531,141.351 1197.29,141.351 1197.29,126.111
  rectangle net NetD3_2: 1197.904,126.043 1205.397,129.285
  rectangle net +48V: 1193.038,143.002 1200.531,146.243
  rectangle net NetD3_2: 1204.073,113.69 1207.646,129.286
  rectangle net NetD3_2: 1193.038,138.176 1200.531,141.417
  rectangle net +5V_DIO: 1122.045,146.05 1126.19,163.576
  rectangle net +48V: 1201.674,152.908 1218.946,165.481
  rectangle net +5V_DIO: 1116.838,145.288 1126.109,148.717
  rectangle net +5V_DIO: 1116.203,145.288 1119.378,152.019
  rectangle net +48V: 1198.411,143.002 1218.946,154.432
  rectangle net +12: 1216.787,113.665 1220.47,121.92
  rectangle net +48V: 1204.595,138.176 1218.946,146.304
  rectangle net +48V: 1199.134,143.002 1218.946,146.685
  rectangle net +5V_FAN: 1105.662,167.386 1109.726,176.276
Layer 1:
  rectangle net +5V: 1132.84,200.406 1140.841,203.962
  rectangle net +5V: 1138.555,181.864 1143,203.962
  rectangle net +5V: 1042.542,113.792 1056.303,115.557
  rectangle net +5V: 1053.228,115.05 1056.276,120.892
  rectangle net +5V: 1042.543,115.062 1045.591,120.904
Bottom Layer:
  rectangle net +5V: 1138.555,181.864 1143,193.167
  rectangle net FGND: 1200.277,127.254 1219.2,136.652
  rectangle net FGND: 1198.118,124.206 1215.517,131.191
  rectangle net FGND: 1195.959,113.792 1203.325,138.176
  rectangle net FGND: 1188.593,129.54 1196.848,154.398
  rectangle net FGND: 1099.82,165.608 1103.757,177.8
  rectangle net FGND: 1097.915,174.879 1103.757,176.276
  rectangle net FGND: 1097.661,174.879 1099.947,177.8
  rectangle net FGND: 1065.403,175.006 1067.308,177.8
  rectangle net FGND: 1065.403,176.657 1099.947,177.8
  rectangle net FGND: 1075.93,174.849 1077.835,177.643
  rectangle net FGND: 1086.612,174.498 1088.517,177.292
  rectangle net FGND: 1097.743,155.067 1099.312,166.624
  rectangle net FGND: 1097.843,164.846 1109.599,166.624
  rectangle net FGND: 1097.28,155.067 1099.185,157.861
  rectangle net FGND: 1086.612,154.813 1088.517,157.607
  rectangle net FGND: 1075.93,155.164 1077.835,157.958
  rectangle net FGND: 1065.403,156.972 1099.185,158.115
  rectangle net FGND: 1065.403,155.321 1067.308,158.115

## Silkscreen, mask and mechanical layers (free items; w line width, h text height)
Top Overlay:
  drawing of 40 lines, arcs and shapes, not listed
  text "TX LED" at 1185.164,199.39 h0.6 r270
  text "RX LED" at 1197.102,199.263 h0.6 r270
  text "info@kryptonsolutions.com.pk" at 951.457,195.782 h3
  text "+" at 1189.99,184.507 h3
  text "+5V POWER" at 1183.513,183.007 h0.7
  text "+" at 1134.491,177.522 h3
  text "GND" at 1192.911,176.276 h0.7
  text "+5V" at 1205.103,176.022 h0.7
  text "+" at 1226.058,167.489 h3
  text "CAUTION INSTALLED WITH LIFTED LEGS" at 1185.799,155.956 h0.7
  text "ECO.I V 1.1 DEC 25" at 949.019,147.547 h3 r90
  text "A" at 1185.84,121.743 h0.9
  text "B" at 1193.653,121.726 h0.9
  text "-VE" at 1197.356,121.412 h0.9
  text "+VE" at 1208.024,121.412 h0.9
  text "-" at 1122.045,120.892 h6
  text "TC2" at 1137.666,120.452 h5
  text "+" at 1118.108,120.349 h6
  text "TC1" at 1093.894,119.519 h5
  text "+VE" at 1221.494,118.441 h0.9
  text "-" at 1099.845,114.511 h6
  text "+" at 1140.028,114.057 h6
